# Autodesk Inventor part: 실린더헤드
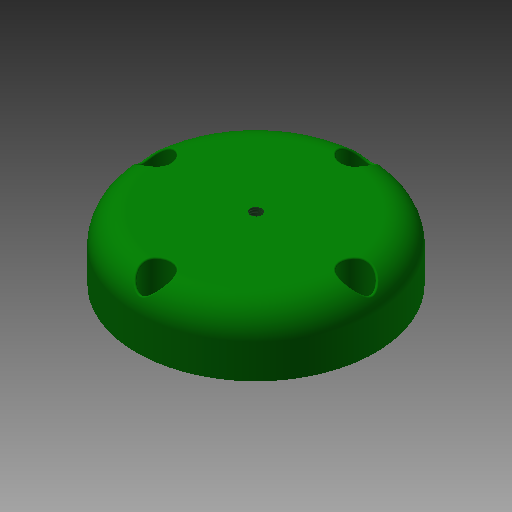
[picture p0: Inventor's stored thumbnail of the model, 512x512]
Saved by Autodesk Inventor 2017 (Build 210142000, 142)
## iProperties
Created: 2016-11
Part Number: 실린더헤드
Material: 알루미늄 6061
Document SubType Name: Modeling
Designer: mduedu
Density: 2.71 g/cm^3
Mass: 235.592 g
Surface Area: 209.258 cm^2
Volume: 86.9344 cm^3
Appearance: 진녹색
Author: mduedu
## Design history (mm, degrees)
sketch "스케치1"
  geometry: C1 r 42 at (0, 0); 1 further point
  constraints: 1 centre point, 1 coincident
  dimensions: "d0" = 84 diameter of C1
extrude "돌출1" new body sketch "스케치1" distance "d1" = 22; taper "d2" = 0 deg
fillet "모깎기1" dims "d3" = 10
sketch "스케치2"
  geometry: C1 r 30 at (0, 0); 1 further point
  constraints: 1 centre point, 1 coincident
  dimensions: "d4" = 60 diameter of C1
extrude "돌출2" join sketch "스케치2" distance "d5" = 5; taper "d6" = 0 deg
sketch "스케치3"
  geometry: C1 r 25 at (0, 0); 1 further point
  constraints: 1 centre point, 1 coincident
  dimensions: "d7" = 50 diameter of C1
extrude "돌출3" cut sketch "스케치3" distance "d8" = 18; taper "d9" = 0 deg
hole "구멍1" diameter "d12" = 4.134; stored, may be unused: countersink angle "d16" = 90 deg, drill point angle "d18" = 118 deg; dims "d10" = 10, "d11" = 10, "d13" = 6, "d14" = 4, "d15" = 2, "d17" = 8
chamfer "모따기1" distance "d19" = 1; stored, may be unused: second distance "d20" = 2, angle "d21" = 45 deg
fillet "모깎기2" dims "d22" = 3
sketch "스케치4"
  geometry: C1 r 17.5 at (0, 0); 1 further point
  constraints: 1 centre point, 1 coincident
  dimensions: "d23" = 35 diameter of C1
extrude "돌출4" cut sketch "스케치4" distance "d24" = 3; taper "d25" = 0 deg
fillet "모깎기3" dims "d26" = 0.5
sketch "스케치5" dims "d32" = 70
  geometry: C1 r 5 at (0, 35); 3 further points
  constraints: 2 coincident, 2 vertical alignment, 1 centre point, 2 other
  dimensions: "d33" = 10 diameter of C1
extrude "돌출5" cut sketch "스케치5" distance "d34" = 12; taper "d35" = 0 deg
sketch "스케치6" dims "d39" = 70
  geometry: 6 further points
  constraints: 2 vertical alignment, 1 coincident, 7 other
  dimensions: "d42" = 360 deg dimension on point (0, -35) point (0, 0) (derived)
sketch "스케치7"
  geometry: 4 further points
  constraints: 4 other
hole "구멍2" sketch "스케치7" at (0, 70), (-35, 35), (35, 35), (0, 0) diameter "d44" = 5.5; stored, may be unused: countersink angle "d48" = 90 deg, drill point angle "d50" = 0 deg; dims "d45" = 6, "d46" = 4, "d47" = 2, "d49" = 8
fillet "모깎기4" dims "d51" = 0.5
chamfer "모따기2" distance "d54" = 5; stored, may be unused: second distance "d55" = 2, angle "d56" = 30 deg
node "솔리드1"
pattern_circular "원형 패턴1" dims angle "d37" = 360 deg
